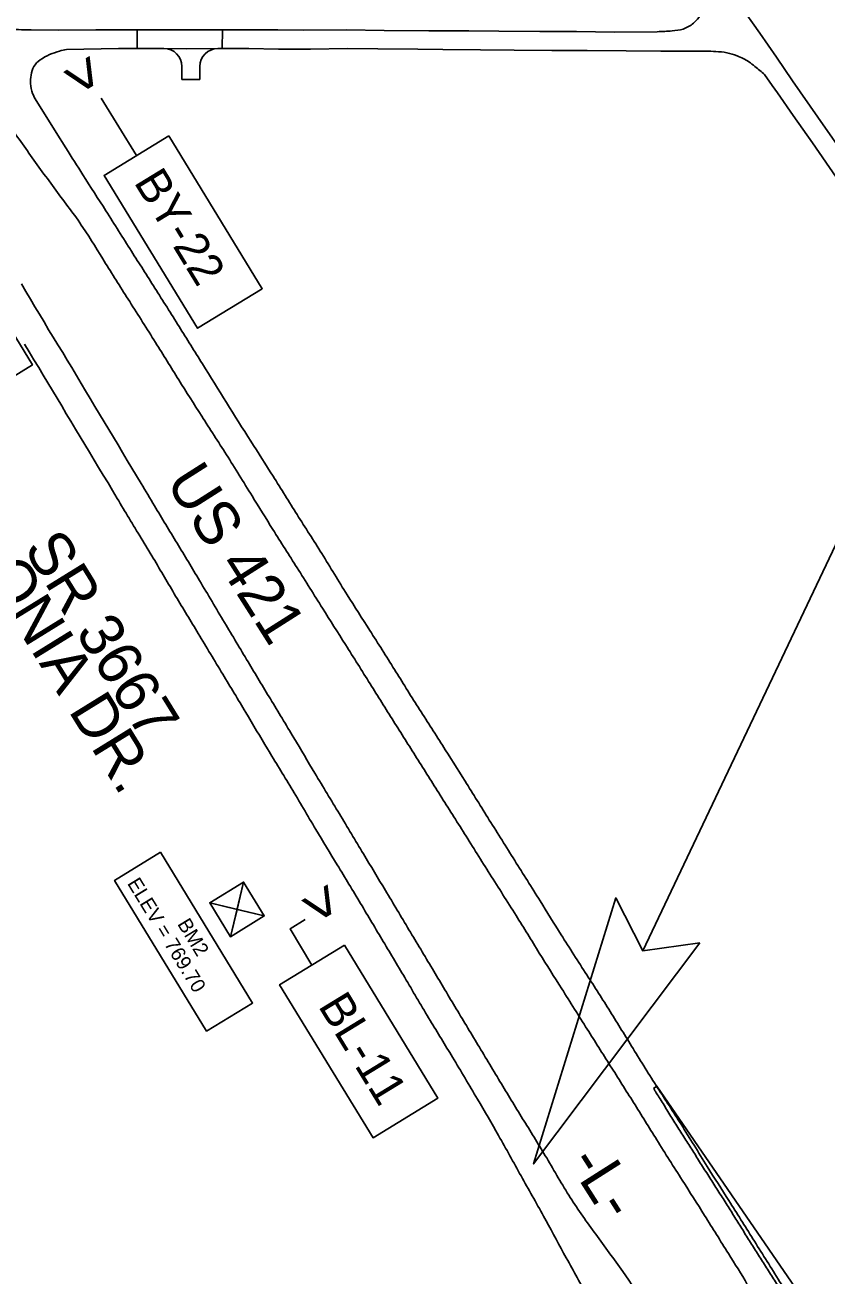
# Model space of a CAD drawing. Extents: x 1771071 to 1790027, y 804210 to 823391.
# Drawn here: x 1780578 to 1781471, y 814333 to 815725 of the extents above; entities that cross this region are included whole.
import ezdxf

# ---------------------------------------------------------------- set-up
doc = ezdxf.new("R2010")
doc.units = 0
for name, color, linetype in [('Default', 7, 'Continuous'), ('Exist Roads EOP', 7, 'Continuous'), ('Old_Level_57', 7, 'Continuous'), ('Prop Conc 5in Monolithic Surface Mount Island', 7, 'Continuous'), ('Prop Conc Shoulder Berm Gutter', 7, 'Continuous'), ('Prop Superelevation Label', 7, 'Continuous'), ('Proposed Right of Way Monument PSD Text', 7, 'Continuous'), ('Scratch_Level_7', 7, 'Continuous'), ('Scratch_Level_8', 7, 'Continuous')]:
    doc.layers.add(name, color=color, linetype=linetype)

msp = doc.modelspace()

# ---------------------------------------------------------------- linework, layer by layer
at = {"layer": 'Default'}
for points in [[(1780702.2, 815579.8), (1780702.2, 815579.8), (1780662.9, 815643.9)], [(1780890.1, 814728.8), (1780873.4, 814718.4), (1780897.8, 814678.1)]]:
    msp.add_lwpolyline(points, dxfattribs=at)
for points in [[(1780738.3, 815601.9), (1780842.4, 815431.5), (1780770.3, 815387.4), (1780666.1, 815557.8)], [(1780445, 815578), (1780586.3, 815346.7), (1780530.6, 815312.6), (1780389.3, 815544)], [(1780729, 814803.8), (1780831.6, 814635.8), (1780780.4, 814604.5), (1780677.8, 814772.5)], [(1780933.9, 814700.2), (1781038, 814529.8), (1780965.9, 814485.7), (1780861.7, 814656.1)]]:
    msp.add_lwpolyline(points, close=True, dxfattribs=at)
at = {"layer": 'Exist Roads EOP'}
msp.add_line((1781402.1, 815670.3), (1781410.6, 815658), dxfattribs=at)
for points in [[(1781415.2, 815689.4), (1781396.7, 815716.1), (1781374.3, 815748.2), (1781355.5, 815775.1), (1781330.6, 815810.8), (1781304.8, 815848), (1781279.6, 815884.3), (1781259.6, 815912.7), (1781239.5, 815941.9), (1781221.1, 815968.2)], [(1780825.4, 815719.9), (1780786.5, 815719.8), (1780741.3, 815720), (1780700.1, 815719.8), (1780656.8, 815719.8), (1780615.4, 815719.7), (1780584.9, 815720)], [(1781282.5, 815717.8), (1781234.9, 815717.3), (1781192.4, 815717.9), (1781151.6, 815718), (1781106, 815718.6), (1781072.4, 815718.7), (1781028.1, 815718.8), (1780978.4, 815719.1), (1780936.2, 815719.8), (1780888.9, 815719.5), (1780859.7, 815719.8), (1780825.4, 815719.9)], [(1780624.3, 815698.1), (1780643.7, 815698.5), (1780682.2, 815699.1), (1780713, 815699.2), (1780758.2, 815698.9), (1780796.2, 815699), (1780827.4, 815699), (1780860.6, 815698.4)], [(1780860.6, 815698.4), (1780896.3, 815698.5), (1780937.3, 815699), (1780971.2, 815698.8), (1781015.8, 815698.5), (1781043.7, 815698), (1781085.4, 815697.8), (1781123, 815697.4), (1781165.2, 815697), (1781204.4, 815696.8), (1781247.9, 815696.4), (1781286.5, 815696.1), (1781325.7, 815696.2)], [(1781722.4, 815246.8), (1781688.8, 815295.1), (1781654.5, 815344.9), (1781637.1, 815370), (1781600.6, 815422.3), (1781565.9, 815472.4), (1781532, 815521.1), (1781496.6, 815572.1), (1781461.4, 815622.8), (1781433.3, 815663.2), (1781415.2, 815689.4)], [(1781629.5, 815343.1), (1781614.2, 815365.3), (1781592.8, 815395.6), (1781566.8, 815433.3), (1781542.5, 815468.2), (1781507.5, 815518.7), (1781481.8, 815555.6), (1781455.3, 815594.1), (1781434.1, 815624.5), (1781416.5, 815649.9), (1781410.6, 815658)], [(1780623.7, 815588.3), (1780612.9, 815605.5), (1780598.5, 815628.2), (1780590.4, 815641.1)], [(1780574, 815437), (1780579.1, 815428.6), (1780584.3, 815420), (1780589.2, 815411.5), (1780594.2, 815403.1), (1780599.4, 815394.5), (1780604.3, 815385.9), (1780609.6, 815377.7), (1780614.8, 815369.1), (1780620.1, 815360.5), (1780625.1, 815351.9), (1780630.3, 815343.6), (1780635.4, 815334.8), (1780640.5, 815326), (1780645.6, 815317.7), (1780650.8, 815309.1), (1780655.9, 815300.3), (1780661.1, 815291.6), (1780666.2, 815283.1), (1780671.4, 815274.7), (1780676.6, 815266), (1780681.7, 815257.5), (1780686.8, 815248.9), (1780691.9, 815240.3), (1780697.1, 815231.6), (1780702.3, 815223.1), (1780707.5, 815214.7)], [(1780577.6, 815369.6), (1780582.7, 815361.1), (1780588, 815352.2), (1780593.3, 815343.7), (1780598.3, 815335.4), (1780603.6, 815326.8), (1780608.7, 815318.1), (1780613.8, 815309.7), (1780619.1, 815300.9), (1780624, 815292.3), (1780629.3, 815283.8), (1780634.4, 815275), (1780639.5, 815266.6), (1780644.8, 815258), (1780649.8, 815249.4), (1780655.1, 815240.7), (1780660, 815232.5), (1780665.1, 815223.9), (1780670.7, 815215.2), (1780675.6, 815206.7), (1780680.8, 815197.9)]]:
    msp.add_lwpolyline(points, dxfattribs=at)
for points in [[(1781328.7, 815776.4), (1781333.1, 815769.3), (1781334.8, 815759.8), (1781334.3, 815750.8), (1781333.6, 815744.6), (1781328.8, 815733.7), (1781322.8, 815727.3), (1781311.4, 815720.8), (1781299.1, 815718.7), (1781282.5, 815717.8)], [(1780584.9, 815720), (1780570.7, 815720.1), (1780555.3, 815721.9), (1780547, 815724.2), (1780535.8, 815731.4), (1780527.5, 815740.7)], [(1780590.4, 815641.1), (1780586.6, 815649.1), (1780584.1, 815660), (1780584.8, 815669.5), (1780587.9, 815679), (1780594.9, 815686.4), (1780605.4, 815692.3), (1780616.6, 815696.2), (1780624.3, 815698.1)], [(1781325.7, 815696.2), (1781347.8, 815695.8), (1781360.2, 815694.3), (1781371.5, 815691), (1781384.5, 815684.3), (1781391.4, 815679.1), (1781402.1, 815670.3)], [(1780506.7, 815662.6), (1780508.5, 815662.6), (1780522, 815663.3), (1780526.2, 815661.7), (1780532, 815652.7), (1780552.8, 815622.9), (1780582.5, 815582.6), (1780612.4, 815541.3), (1780642.6, 815499.8), (1780667.9, 815459.7), (1780694.7, 815417.2), (1780723.5, 815371.6), (1780749.4, 815330), (1780774.9, 815289.7), (1780802.5, 815246.6), (1780831, 815200.8), (1780854.3, 815163.2), (1780881.3, 815120.6), (1780909.6, 815075.5), (1780935.1, 815035.1), (1780962.6, 814991.4), (1780988.6, 814949.9), (1781014.4, 814909), (1781040.7, 814867.2), (1781067.8, 814824.4), (1781096, 814779.4), (1781125.2, 814733.4), (1781151.1, 814691.5), (1781176.1, 814651.7), (1781204.5, 814606.6), (1781230.2, 814566), (1781256.1, 814524.9), (1781282, 814483.3), (1781310.3, 814438.6), (1781335.3, 814399.1), (1781361.8, 814356.7), (1781382.8, 814322.4), (1781389.5, 814309.4), (1781392.1, 814297.9), (1781391.6, 814294.9)], [(1780623.7, 815588.3), (1780642.6, 815558.3), (1780668.2, 815518.3), (1780696.6, 815473.4), (1780722.8, 815432.2), (1780749.7, 815389.4), (1780775.7, 815347.7), (1780829.6, 815261.7), (1780854.4, 815222.7), (1780881.2, 815179.9), (1780908.8, 815136.4), (1780936.9, 815090.7), (1780962.3, 815050.8), (1780989.7, 815007.3), (1781016, 814965.5), (1781043.2, 814923), (1781068.3, 814883.1), (1781095.4, 814839.7), (1781123.7, 814794.6)], [(1781302, 814247.2), (1781298.8, 814253.2), (1781270.8, 814297.7), (1781244, 814336.6), (1781214, 814378.2), (1781185.6, 814419.1), (1781159.3, 814463.2), (1781134.1, 814504.4), (1781108.9, 814545.7), (1781082.7, 814589.3), (1781057, 814632), (1781031.9, 814674), (1781005.9, 814717.4), (1780979.7, 814761.2), (1780955.2, 814801.9), (1780928.3, 814846.6), (1780901.1, 814891.7), (1780877.5, 814931.4), (1780851.5, 814974.5), (1780826.6, 815015.9), (1780800.4, 815059.6), (1780772.5, 815106.5), (1780747.5, 815148), (1780722.3, 815189.6), (1780707.5, 815214.7)], [(1780680.8, 815197.9), (1780694, 815175.8), (1780721, 815131.3), (1780745.9, 815089.2), (1780771.1, 815047.4), (1780798.4, 815002.1), (1780824, 814959.6), (1780848.3, 814918.8), (1780874.6, 814875.6), (1780902.1, 814829.2), (1780926, 814789.7), (1780952, 814746.6), (1780977.3, 814704.3), (1781002.8, 814661.4), (1781029.4, 814616.5), (1781054.5, 814575.4), (1781082.1, 814528.8), (1781105.7, 814488.2), (1781130.7, 814443.3), (1781155.8, 814398.5), (1781178.2, 814357.3), (1781202.4, 814313.6), (1781227.3, 814269.7), (1781240.7, 814246.1)], [(1781123.7, 814794.6), (1781151.9, 814749.7), (1781175.4, 814711.9), (1781204, 814667.2), (1781230.1, 814626.4), (1781255.5, 814585.1), (1781282.9, 814541.4), (1781309, 814500.8), (1781338.1, 814453.8), (1781362.4, 814415.7), (1781389.1, 814373.2), (1781417.2, 814328.4), (1781443.8, 814286), (1781469.2, 814245.3), (1781496.3, 814201.9), (1781523.3, 814159.3), (1781551.5, 814114.9), (1781575, 814076.8), (1781602.3, 814034.5), (1781628.7, 813992.4), (1781657.7, 813946.4), (1781683, 813906.2), (1781710.5, 813862.1), (1781734.7, 813823.6), (1781763.1, 813779.2), (1781788.4, 813738.4), (1781814.8, 813696.3), (1781842.4, 813653.4), (1781868.9, 813610.7), (1781895.8, 813568.7), (1781924.4, 813523.6), (1781950.6, 813481.8), (1781976.7, 813442.7), (1782004.4, 813401.4), (1782032, 813360.1), (1782060.8, 813317.5), (1782089.2, 813276.6), (1782119.2, 813233.3), (1782146.2, 813195.7), (1782175.1, 813155.1), (1782204.1, 813115.4), (1782233.2, 813075.7), (1782263.8, 813034.4), (1782294, 812994.3), (1782325, 812953.9), (1782354.4, 812916.2), (1782385, 812877.4), (1782417.2, 812837.3), (1782449.4, 812797.6), (1782479.5, 812761.8), (1782513.2, 812720.7), (1782543, 812685), (1782576.4, 812645.9), (1782608.5, 812608.7), (1782640.7, 812571.4), (1782677.4, 812531), (1782710.3, 812494.7), (1782741.2, 812460.8), (1782775.5, 812424.1), (1782810.1, 812387), (1782844.4, 812350.7), (1782880.7, 812313.2), (1782914.8, 812277.6), (1782949.9, 812242.2), (1782985.1, 812206.9), (1783022.4, 812170.4), (1783054.9, 812138.6), (1783094.7, 812100.5), (1783130, 812066.9), (1783162.7, 812036.2), (1783200.8, 812001.5), (1783239.6, 811966), (1783275.5, 811933.3), (1783312.5, 811900.8)]]:
    msp.add_spline(points, degree=3, dxfattribs=at)
at = {"layer": 'Old_Level_57'}
for p, q in [((1780806.9, 814709.7), (1780821.6, 814770.5)), ((1780844.7, 814732.8), (1780783.9, 814747.5))]:
    msp.add_line(p, q, dxfattribs=at)
msp.add_lwpolyline([(1780821.6, 814770.5), (1780783.9, 814747.5), (1780806.9, 814709.7), (1780844.7, 814732.8)], close=True, dxfattribs=at)
for points in [[(1780814.3, 814740.1), (1780821.6, 814770.5), (1780783.9, 814747.5), (1780814.3, 814740.1)], [(1780814.3, 814740.1), (1780806.9, 814709.7), (1780844.7, 814732.8), (1780814.3, 814740.1)]]:
    msp.add_lwpolyline(points, dxfattribs=at)
at = {"layer": 'Prop Conc 5in Monolithic Surface Mount Island'}
for p, q in [((1780703, 815719.8), (1780702.9, 815699.2)), ((1780703, 815719.8), (1780741.3, 815720)), ((1780741.3, 815720), (1780786.5, 815719.8)), ((1780786.5, 815719.8), (1780798, 815719.9)), ((1780798, 815719.9), (1780797.9, 815699)), ((1780702.9, 815699.2), (1780713, 815699.2)), ((1780713, 815699.2), (1780732.9, 815699.1)), ((1780797.9, 815699), (1780792.8, 815699)), ((1780752.8, 815679), (1780752.7, 815664.5)), ((1780772.8, 815679.1), (1780772.7, 815664.4)), ((1780772.7, 815664.4), (1780752.7, 815664.5))]:
    msp.add_line(p, q, dxfattribs=at)
for centre, start, end in [((1780732.8, 815679.1), 359.7234, 89.6675), ((1780792.8, 815679), 90.0588, 179.7234)]:
    msp.add_arc(centre, 20, start, end, dxfattribs=at)
at = {"layer": 'Prop Conc Shoulder Berm Gutter'}
msp.add_line((1781266.5, 814693.9), (1781796, 815809.5), dxfattribs=at)
at = {"layer": 'Prop Superelevation Label'}
msp.add_lwpolyline([(1781330, 814703), (1781144.7, 814456.7), (1781236.2, 814753), (1781266.5, 814693.9)], close=True, dxfattribs=at)
at = {"layer": 'Scratch_Level_8'}
for p, q in [((1780703, 815719.8), (1780702.9, 815699.2)), ((1780741.3, 815720), (1780703, 815719.8)), ((1780786.5, 815719.8), (1780741.3, 815720)), ((1780798, 815719.9), (1780786.5, 815719.8)), ((1780797.9, 815699), (1780798, 815719.9)), ((1780702.9, 815699.2), (1780713, 815699.2)), ((1780713, 815699.2), (1780732.9, 815699.1)), ((1780792.8, 815699), (1780797.9, 815699)), ((1780752.8, 815679), (1780752.7, 815664.5)), ((1780772.7, 815664.4), (1780772.8, 815679.1)), ((1780752.7, 815664.5), (1780772.7, 815664.4)), ((1781281.9, 814543.1), (1781278.2, 814540.8)), ((1781278.2, 814540.8), (1781281.9, 814543.1)), ((1781281.9, 814543.1), (1781452.3, 814295.9))]:
    msp.add_line(p, q, dxfattribs=at)
for centre, start, end in [((1780732.8, 815679.1), 359.7234, 89.6675), ((1780792.8, 815679), 90.0588, 179.7234)]:
    msp.add_arc(centre, 20, start, end, dxfattribs=at)
msp.add_open_spline([(1782036.8, 813345.3), (1782034.5, 813348.7), (1782032.3, 813352.1), (1782030, 813355.5), (1782020.7, 813369.4), (1782011.4, 813383.3), (1782002.1, 813397.2), (1781993, 813410.9), (1781983.9, 813424.5), (1781974.9, 813438.2), (1781965.3, 813452.8), (1781955.8, 813467.5), (1781946.3, 813482.2), (1781937.6, 813495.6), (1781928.9, 813509), (1781920.3, 813522.4), (1781911.2, 813536.5), (1781902.4, 813550.8), (1781893.4, 813564.9), (1781884.4, 813579), (1781875.1, 813592.8), (1781866.2, 813606.9), (1781857.4, 813621.1), (1781848.5, 813635.2), (1781839.6, 813649.4), (1781830.6, 813663.7), (1781821.5, 813678.1), (1781812.5, 813692.5), (1781803.9, 813706.2), (1781795.2, 813720), (1781786.6, 813733.7), (1781777.5, 813748.2), (1781768.1, 813762.6), (1781758.9, 813777.2), (1781750.1, 813791.2), (1781741.3, 813805.3), (1781732.5, 813819.4), (1781723.6, 813833.5), (1781714.7, 813847.6), (1781705.8, 813861.7), (1781697, 813875.8), (1781688.1, 813890), (1781679.3, 813904.1), (1781670.6, 813918), (1781662.1, 813932), (1781653.4, 813945.8), (1781644.8, 813959.6), (1781636.1, 813973.4), (1781627.4, 813987.2), (1781618.4, 814001.5), (1781609.3, 814015.9), (1781600.3, 814030.2), (1781591.2, 814044.6), (1781582, 814058.8), (1781572.9, 814073.2), (1781564, 814087.3), (1781555.4, 814101.5), (1781546.5, 814115.6), (1781537.6, 814129.7), (1781528.6, 814143.7), (1781519.7, 814157.8), (1781510.8, 814171.9), (1781502.1, 814186.2), (1781493.2, 814200.3), (1781484.6, 814213.9), (1781475.8, 814227.5), (1781467.1, 814241.1), (1781457.9, 814255.8), (1781448.7, 814270.6), (1781439.4, 814285.2), (1781430.6, 814299.1), (1781421.8, 814313), (1781413, 814326.9), (1781404.1, 814341), (1781395.2, 814355), (1781386.4, 814369.1), (1781377.7, 814383), (1781369.1, 814396.9), (1781360.3, 814410.7), (1781351.3, 814425.1), (1781342.1, 814439.4), (1781333, 814453.8), (1781324.2, 814467.7), (1781315.4, 814481.5), (1781306.7, 814495.4), (1781297.8, 814509.6), (1781288.9, 814523.8), (1781280.1, 814537.9), (1781279.5, 814538.9), (1781278.8, 814539.9), (1781278.2, 814540.8)], degree=3, dxfattribs=at)

# ---------------------------------------------------------------- texts
at = {"layer": 'Old_Level_57'}
for p in [(1780614.5, 815672.8), (1780879.7, 814750)]:
    msp.add_text('>', height=47, rotation=301.4392, dxfattribs=at).set_placement(p)
at = {"layer": 'Proposed Right of Way Monument PSD Text'}
for s, height, p in [('BY-22', 37.32, (1780698.7, 815550.3)), ('ELEV = 769.70', 16, (1780691.5, 814769.2)), ('BM2', 16, (1780747.3, 814723.9)), ('BL-11', 37.32, (1780904.1, 814632.6))]:
    msp.add_text(s, height=height, rotation=301.4249, dxfattribs=at).set_placement(p)
at = {"layer": 'Scratch_Level_7'}
for s, height, rotation, p in [('BEGONIA DR.', 49.208, 301.7096, (1780458.6, 815232.2)), ('US 421', 49.21, 302.4535, (1780733.9, 815216.7)), ('SR 3667', 49.21, 301.7096, (1780575.9, 815142.3)), ('-L-', 49.21, 302.4535, (1781182.4, 814458.4))]:
    msp.add_text(s, height=height, rotation=rotation, dxfattribs=at).set_placement(p)

doc.saveas('drawing.dxf')
